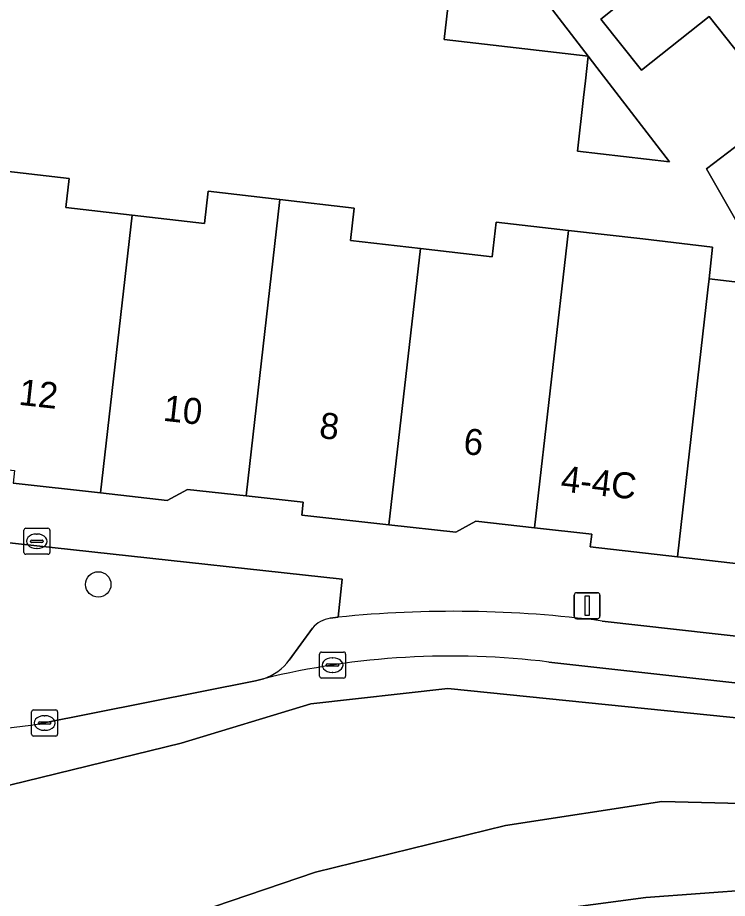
# Model space of a CAD drawing. Extents: x 160663 to 161506, y 382245 to 383291.
# Drawn here: x 160879.22 to 160906.51, y 382930.82 to 382964.66 of the extents above; entities that cross this region are included whole.
import ezdxf

# ---------------------------------------------------------------- set-up
doc = ezdxf.new("R2010")
doc.units = 0
for name, color, linetype in [('IMGEO_Boom', 7, 'Continuous'), ('IMGEO_Erf', 7, 'Continuous'), ('IMGEO_Fietspad_gesloten', 7, 'Continuous'), ('IMGEO_Groenvoorziening', 7, 'Continuous'), ('IMGEO_Kolk', 7, 'Continuous'), ('IMGEO_Lichtmast', 7, 'Continuous'), ('IMGEO_OVBaan_gesloten', 7, 'Continuous'), ('IMGEO_Pand', 7, 'Continuous'), ('IMGEO_Pand_nummerreeks', 7, 'Continuous'), ('IMGEO_Parkeervlak_open', 7, 'Continuous'), ('IMGEO_Rijbaan_lokaal_gesloten', 7, 'Continuous'), ('IMGEO_Voetpad_open', 7, 'Continuous')]:
    doc.layers.add(name, color=color, linetype=linetype)

msp = doc.modelspace()

# ---------------------------------------------------------------- linework, layer by layer
at = {"layer": 'IMGEO_Boom'}
msp.add_circle((160882.322, 382942.885), 0.489, dxfattribs=at)
at = {"layer": 'IMGEO_Erf'}
for points in [[(160901.164, 382963.177), (160895.621, 382963.817), (160896.271, 382969.534)], [(160901.493, 382962.749), (160904.283, 382959.124), (160900.749, 382959.532), (160900.984, 382961.594), (160901.057, 382962.239), (160901.164, 382963.177)]]:
    msp.add_lwpolyline(points, close=True, dxfattribs=at)
for points in [[(160908.24, 382954.436), (160905.706, 382958.852), (160908.677, 382961.103), (160905.809, 382964.709), (160903.21, 382962.641), (160901.649, 382964.603), (160905.909, 382967.992), (160910.338, 382962.425)], [(160878.202, 382958.832), (160881.198, 382958.486), (160881.07, 382957.37), (160883.62, 382957.076), (160886.402, 382956.755), (160886.545, 382957.993), (160889.305, 382957.674), (160892.16, 382957.345), (160892.017, 382956.103), (160894.708, 382955.793), (160897.47, 382955.474), (160897.624, 382956.809), (160900.403, 382956.488), (160903.261, 382956.158), (160905.948, 382955.848), (160905.808, 382954.621), (160908.104, 382954.357)]]:
    msp.add_lwpolyline(points, dxfattribs=at)
at = {"layer": 'IMGEO_Fietspad_gesloten'}
msp.add_lwpolyline([(160961.035, 382926.32), (160957.674, 382927.094), (160935.566, 382928.505), (160911.678, 382931.189), (160907.553, 382931.166), (160903.382, 382930.863), (160897.497, 382930.071), (160888.563, 382927.461), (160885.812, 382926.048), (160887.39, 382924.302)], dxfattribs=at)
at = {"layer": 'IMGEO_Groenvoorziening'}
for points in [[(160891.244, 382941.588), (160891.553, 382941.627), (160891.701, 382943.093), (160872.431, 382945.192)], [(160889.668, 382939.976), (160890.554, 382941.21)], [(160880.045, 382937.526), (160888.371, 382939.187), (160888.68, 382939.263)]]:
    msp.add_lwpolyline(points, dxfattribs=at)
for centre, radius, start, end in [((160891.456, 382940.382), 1.225, 99.9829, 137.4473), ((160888.049, 382941.178), 2.017, 288.2331, 323.3998), ((160876.344, 382962.262), 25.011, 266.7469, 278.5089)]:
    msp.add_arc(centre, radius, start, end, dxfattribs=at)
at = {"layer": 'IMGEO_Kolk'}
for p, q in [((160879.459, 382944.117), (160879.459, 382944.969)), ((160879.534, 382945.043), (160880.386, 382945.043)), ((160879.947, 382944.823), (160879.972, 382944.823)), ((160880.46, 382944.969), (160880.46, 382944.117)), ((160879.718, 382944.537), (160879.718, 382944.549)), ((160880.156, 382944.5), (160879.758, 382944.5)), ((160879.761, 382944.586), (160880.159, 382944.586)), ((160880.202, 382944.549), (160880.202, 382944.537)), ((160879.97, 382944.263), (160879.945, 382944.263)), ((160880.386, 382944.043), (160879.534, 382944.043)), ((160890.831, 382939.36), (160890.831, 382940.212)), ((160890.906, 382940.286), (160891.758, 382940.286)), ((160891.319, 382940.066), (160891.344, 382940.066)), ((160891.832, 382940.212), (160891.832, 382939.36)), ((160891.09, 382939.78), (160891.09, 382939.792)), ((160891.528, 382939.743), (160891.13, 382939.743)), ((160891.133, 382939.829), (160891.531, 382939.829)), ((160891.574, 382939.792), (160891.574, 382939.78)), ((160891.342, 382939.506), (160891.317, 382939.506)), ((160891.758, 382939.286), (160890.906, 382939.286)), ((160879.758, 382937.135), (160879.758, 382937.987)), ((160879.833, 382938.061), (160880.685, 382938.061)), ((160880.759, 382937.987), (160880.759, 382937.135)), ((160880.246, 382937.841), (160880.271, 382937.841)), ((160880.017, 382937.555), (160880.017, 382937.567)), ((160880.455, 382937.518), (160880.057, 382937.518)), ((160880.06, 382937.604), (160880.458, 382937.604)), ((160880.501, 382937.567), (160880.501, 382937.555)), ((160880.685, 382937.061), (160879.833, 382937.061)), ((160880.269, 382937.281), (160880.244, 382937.281))]:
    msp.add_line(p, q, dxfattribs=at)
for points in [[(160879.459, 382944.117), (160879.459, 382944.969)], [(160879.534, 382945.043), (160880.386, 382945.043)], [(160880.46, 382944.969), (160880.46, 382944.117)], [(160880.386, 382944.043), (160879.534, 382944.043)], [(160890.831, 382939.36), (160890.831, 382940.212)], [(160890.906, 382940.286), (160891.758, 382940.286)], [(160891.832, 382940.212), (160891.832, 382939.36)], [(160891.758, 382939.286), (160890.906, 382939.286)], [(160879.758, 382937.135), (160879.758, 382937.987)], [(160879.833, 382938.061), (160880.685, 382938.061)], [(160880.759, 382937.987), (160880.759, 382937.135)], [(160880.685, 382937.061), (160879.833, 382937.061)]]:
    msp.add_lwpolyline(points, dxfattribs=at)
for centre, radius, start, end in [((160879.536, 382944.967), 0.0765, 91.552, 178.448), ((160879.536, 382944.967), 0.0765, 91.552, 178.448), ((160880.384, 382944.967), 0.0765, 1.552, 88.448), ((160880.384, 382944.967), 0.0765, 1.552, 88.448), ((160879.758, 382944.546), 0.0403, 85.8775, 175.7526), ((160879.755, 382944.536), 0.0366, 178.938, 274.7102), ((160880.159, 382944.543), 0.043, 264.8664, 352.4533), ((160880.163, 382944.548), 0.0386, 1.7309, 96.639), ((160879.536, 382944.119), 0.0765, 181.552, 268.448), ((160879.536, 382944.119), 0.0765, 181.552, 268.448), ((160880.384, 382944.119), 0.0765, 271.552, 358.448), ((160880.384, 382944.119), 0.0765, 271.552, 358.448), ((160890.908, 382940.21), 0.0765, 91.552, 178.448), ((160890.908, 382940.21), 0.0765, 91.552, 178.448), ((160891.756, 382940.21), 0.0765, 1.552, 88.448), ((160891.756, 382940.21), 0.0765, 1.552, 88.448), ((160891.13, 382939.789), 0.0403, 85.8775, 175.7526), ((160891.127, 382939.779), 0.0366, 178.938, 274.7102), ((160891.531, 382939.786), 0.043, 264.8664, 352.4533), ((160891.535, 382939.791), 0.0386, 1.7309, 96.639), ((160890.908, 382939.362), 0.0765, 181.552, 268.448), ((160890.908, 382939.362), 0.0765, 181.552, 268.448), ((160891.756, 382939.362), 0.0765, 271.552, 358.448), ((160891.756, 382939.362), 0.0765, 271.552, 358.448), ((160879.835, 382937.985), 0.0765, 91.552, 178.448), ((160879.835, 382937.985), 0.0765, 91.552, 178.448), ((160880.683, 382937.985), 0.0765, 1.552, 88.448), ((160880.683, 382937.985), 0.0765, 1.552, 88.448), ((160880.057, 382937.564), 0.0403, 85.8775, 175.7526), ((160880.054, 382937.554), 0.0366, 178.938, 274.7102), ((160880.458, 382937.561), 0.043, 264.8664, 352.4533), ((160880.462, 382937.566), 0.0386, 1.7309, 96.639), ((160879.835, 382937.137), 0.0765, 181.552, 268.448), ((160879.835, 382937.137), 0.0765, 181.552, 268.448), ((160880.683, 382937.137), 0.0765, 271.552, 358.448), ((160880.683, 382937.137), 0.0765, 271.552, 358.448)]:
    msp.add_arc(centre, radius, start, end, dxfattribs=at)
for centre, major_axis, ratio, start_param, end_param in [((160879.946, 382944.543), (-0.387, 0.002), 0.722429, 4.712389, 7.853982), ((160879.971, 382944.543), (-0.39, 0.002), 0.717154, 1.570796, 4.712389), ((160891.318, 382939.786), (-0.387, 0.002), 0.722429, 4.712389, 7.853982), ((160891.343, 382939.786), (-0.39, 0.002), 0.717154, 1.570796, 4.712389), ((160880.245, 382937.561), (-0.387, 0.002), 0.722429, 4.712389, 7.853982), ((160880.27, 382937.561), (-0.39, 0.002), 0.717154, 1.570796, 4.712389)]:
    msp.add_ellipse(centre, major_axis=major_axis, ratio=ratio, start_param=start_param, end_param=end_param, dxfattribs=at)
at = {"layer": 'IMGEO_Lichtmast'}
for p, q in [((160900.625, 382941.668), (160900.625, 382942.468)), ((160900.625, 382942.468), (160900.625, 382941.668)), ((160900.725, 382942.568), (160901.515, 382942.568)), ((160901.515, 382942.568), (160900.725, 382942.568)), ((160901.615, 382942.468), (160901.615, 382941.668)), ((160901.615, 382941.668), (160901.615, 382942.468)), ((160901.515, 382941.568), (160900.725, 382941.568)), ((160900.725, 382941.568), (160901.515, 382941.568))]:
    msp.add_line(p, q, dxfattribs=at)
msp.add_lwpolyline([(160901.045, 382942.443), (160901.195, 382942.443), (160901.195, 382941.693), (160901.045, 382941.693), (160901.045, 382942.443)], dxfattribs=at)
for centre, start, end in [((160900.725, 382942.468), 90, 180), ((160900.725, 382942.468), 90, 180), ((160901.515, 382942.468), 0, 90), ((160901.515, 382942.468), 360, 90), ((160900.725, 382941.668), 180, 270), ((160900.725, 382941.668), 180, 270), ((160901.515, 382941.668), 270, 0), ((160901.515, 382941.668), 270, 0)]:
    msp.add_arc(centre, 0.1, start, end, dxfattribs=at)
at = {"layer": 'IMGEO_OVBaan_gesloten'}
for points in [[(160978.934, 382913.776), (160981.785, 382916.694), (160978.816, 382919.461), (160972.145, 382924.641), (160967.578, 382927.438), (160959.79, 382929.599), (160951.086, 382930.055), (160918.971, 382933.683), (160909.581, 382934.405), (160903.988, 382934.545), (160897.982, 382933.621), (160890.673, 382931.836), (160882.904, 382929.187), (160870.47, 382922.866), (160873.972, 382919.336)], [(160888.563, 382927.461), (160897.497, 382930.071), (160903.382, 382930.863), (160907.553, 382931.166), (160911.678, 382931.189), (160935.566, 382928.505), (160957.674, 382927.094), (160961.035, 382926.32)]]:
    msp.add_lwpolyline(points, dxfattribs=at)
at = {"layer": 'IMGEO_Pand'}
for points in [[(160895.621, 382963.817), (160901.164, 382963.177), (160896.271, 382969.534)], [(160908.677, 382961.103), (160910.338, 382962.425), (160905.909, 382967.992), (160901.649, 382964.603), (160903.21, 382962.641), (160905.809, 382964.709)], [(160901.164, 382963.177), (160901.057, 382962.239), (160900.984, 382961.594), (160900.749, 382959.532), (160904.283, 382959.124), (160901.493, 382962.749)], [(160908.677, 382961.103), (160905.706, 382958.852), (160908.24, 382954.436), (160914.869, 382942.835), (160921.539, 382946.213), (160917.249, 382953.72), (160910.338, 382962.425)], [(160883.62, 382957.076), (160881.07, 382957.37), (160881.198, 382958.486), (160878.202, 382958.832), (160876.915, 382947.51), (160879.105, 382947.269), (160879.05, 382946.772), (160882.405, 382946.401)], [(160889.305, 382957.674), (160886.545, 382957.993), (160886.402, 382956.755), (160883.62, 382957.076), (160882.405, 382946.401), (160884.976, 382946.116), (160885.749, 382946.536), (160888.009, 382946.286)], [(160894.708, 382955.793), (160892.017, 382956.103), (160892.16, 382957.345), (160889.305, 382957.674), (160888.009, 382946.286), (160890.205, 382946.043), (160890.15, 382945.546), (160893.5, 382945.176)], [(160894.708, 382955.793), (160893.5, 382945.176), (160896.066, 382944.892), (160896.838, 382945.312), (160899.103, 382945.063), (160900.403, 382956.488), (160897.624, 382956.809), (160897.47, 382955.474)], [(160905.761, 382954.204), (160905.808, 382954.621), (160905.948, 382955.848), (160903.261, 382956.158), (160900.403, 382956.488), (160899.103, 382945.063), (160901.296, 382944.821), (160901.239, 382944.324), (160904.594, 382943.942)], [(160908.24, 382954.436), (160908.104, 382954.357), (160905.808, 382954.621), (160905.761, 382954.204), (160904.594, 382943.942), (160914.771, 382942.785), (160914.869, 382942.835)]]:
    msp.add_lwpolyline(points, close=True, dxfattribs=at)
at = {"layer": 'IMGEO_Parkeervlak_open'}
for points in [[(160891.553, 382941.627), (160891.244, 382941.588)], [(160943.203, 382937.135), (160914.634, 382940.032), (160913.244, 382940.176), (160901.693, 382941.479)], [(160890.554, 382941.21), (160889.668, 382939.976)], [(160899.65, 382939.904), (160910.957, 382938.648), (160945.978, 382935.062)]]:
    msp.add_lwpolyline(points, dxfattribs=at)
for centre, radius, start, end in [((160895.987, 382897.984), 43.868, 82.5264, 95.8012), ((160891.456, 382940.382), 1.225, 99.9829, 137.4473), ((160895.91, 382909.717), 30.418, 82.9376, 103.7506), ((160888.049, 382941.178), 2.017, 288.2331, 323.3998)]:
    msp.add_arc(centre, radius, start, end, dxfattribs=at)
at = {"layer": 'IMGEO_Rijbaan_lokaal_gesloten'}
for points in [[(160959.055, 382933.734), (160958.649, 382933.764), (160946.296, 382935.03), (160945.978, 382935.062), (160910.957, 382938.648), (160899.65, 382939.904)], [(160888.68, 382939.263), (160888.371, 382939.187), (160880.045, 382937.526)], [(160978.469, 382923.697), (160976.623, 382925.025), (160972.821, 382927.904), (160969.512, 382929.861), (160965.691, 382931.306), (160961.831, 382932.175), (160895.761, 382938.889), (160890.497, 382938.296), (160885.51, 382936.782), (160874.133, 382934.008), (160870.606, 382932.878)], [(160890.497, 382938.296), (160895.761, 382938.889), (160961.831, 382932.175), (160965.691, 382931.306), (160969.512, 382929.861), (160972.821, 382927.904), (160976.623, 382925.025), (160978.469, 382923.697)], [(160874.967, 382934.253), (160874.133, 382934.008), (160885.51, 382936.782), (160890.497, 382938.296)], [(160897.982, 382933.621), (160903.988, 382934.545), (160909.581, 382934.405), (160918.971, 382933.683), (160951.086, 382930.055), (160959.79, 382929.599), (160967.578, 382927.438), (160972.145, 382924.641), (160978.816, 382919.461), (160981.785, 382916.694), (160985.435, 382920.431)], [(160862.06, 382932.256), (160861.66, 382932.461), (160860.049, 382933.373), (160870.47, 382922.866), (160882.904, 382929.187), (160890.673, 382931.836), (160897.982, 382933.621)]]:
    msp.add_lwpolyline(points, dxfattribs=at)
for centre, radius, start, end in [((160895.91, 382909.717), 30.418, 82.9376, 103.7506), ((160876.344, 382962.262), 25.011, 266.7469, 278.5089)]:
    msp.add_arc(centre, radius, start, end, dxfattribs=at)
at = {"layer": 'IMGEO_Voetpad_open'}
for points in [[(160901.693, 382941.479), (160913.244, 382940.176), (160914.634, 382940.032), (160914.869, 382942.835), (160914.771, 382942.785), (160904.594, 382943.942), (160901.239, 382944.324), (160901.296, 382944.821), (160899.103, 382945.063), (160896.838, 382945.312), (160896.066, 382944.892), (160893.5, 382945.176), (160890.15, 382945.546), (160890.205, 382946.043), (160888.009, 382946.286), (160885.749, 382946.536), (160884.976, 382946.116), (160882.405, 382946.401), (160879.05, 382946.772)], [(160872.431, 382945.192), (160891.701, 382943.093), (160891.553, 382941.627)]]:
    msp.add_lwpolyline(points, dxfattribs=at)
msp.add_arc((160895.987, 382897.984), 43.868, 82.5264, 95.8012, dxfattribs=at)

# ---------------------------------------------------------------- texts
at = {"layer": 'IMGEO_Pand_nummerreeks'}
for s, rotation, p in [('12', 353.7001, (160879.233, 382949.792)), ('10', 353.7001, (160884.786, 382949.178)), ('8', 353.7001, (160890.789, 382948.516)), ('6', 353.7001, (160896.332, 382947.905)), ('4-4C', 353.7032, (160900.076, 382946.465))]:
    msp.add_text(s, height=1, rotation=rotation, dxfattribs=at).set_placement(p)

doc.saveas('drawing.dxf')
